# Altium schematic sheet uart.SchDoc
size A4
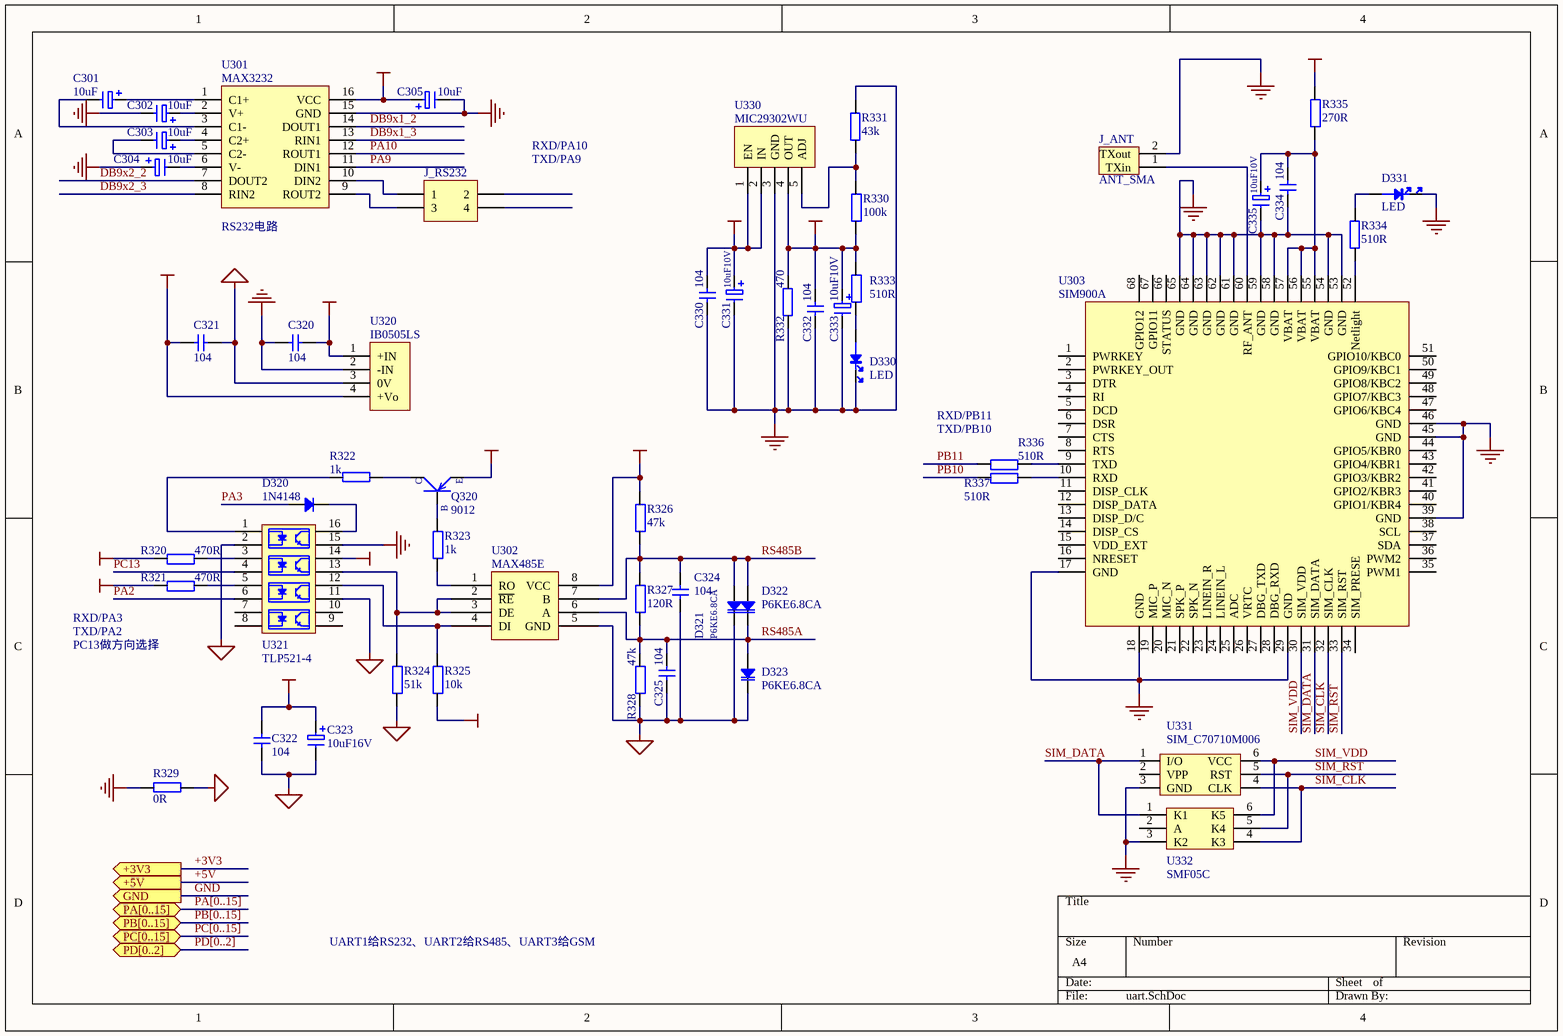
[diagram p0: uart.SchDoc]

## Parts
C301  10uF
C302  10uF
C303  10uF
C304  10uF
C305  10uF
C320  104
C321  104
C322  104
C323  10uF16V
C324  104
C325  104
C330  104
C331  10uF10V
C332  104
C333  10uF10V
C334  104
C335  10uF10V
D320  1N4148  [SOD-123]
D321  P6KE6.8CA  [SOD-123]
D322  P6KE6.8CA  [SOD-123]
D323  P6KE6.8CA  [SOD-123]
D330  LED  [SMDLED]
D331  LED  [SMDLED]
J_ANT  ANT_SMA
J_RS232  Header 2X2  [HDR2X2]  (value not drawn)
Q320  9012  [ZD_TO-92]
R320  470R  [0603P]
R321  470R  [0603P]
R322  1k  [0603P]
R323  1k  [0603P]
R324  51k  [0603P]
R325  10k  [0603P]
R326  47k  [0603P]
R327  120R  [0603P]
R328  47k  [0603P]
R329  0R  [0603P]
R330  100k  [0603P]
R331  43k  [0603P]
R332  470  [0603P]
R333  510R  [0603P]
R334  510R  [0603P]
R335  270R  [0603P]
R336  510R  [0603P]
R337  510R  [0603P]
U301  MAX3232
U302  MAX485E  [DIP8]
U303  SIM900A  [Model Name]
U320  IB0505LS  [IB0505LS]
U321  TLP521-4
U330  MIC29302WU  [TO-263]
U331  SIM_C70710M006  [SIM]
U332  SMF05C  [SOT-363]

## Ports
+3V3 (out), +5V (out), GND (out), PA[0..15] (bidir), PB[0..15] (bidir), PC[0..15] (bidir), PD[0..2] (bidir)

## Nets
+3V3: C305.1 R320.1 R321.1 U301.16(VCC) ; port +3V3
+5V: C320.2 C330.1 C331.1 U320.1(+IN) U330.1(EN) U330.2(IN) ; port +5V
GND: C302.2 C304.1 C305.2 C320.1 C330.2 C331.2 C332.2 C333.2 C334.2 C335.2 D330.2(K) D331.2(K) J_ANT.2(TXout) R329.2 R331.1 R332.2 U301.15(GND) U303.17(GND) U303.18(GND) U303.29(GND) U303.39(GND) U303.45(GND) U303.46(GND) U303.53(GND) U303.54(GND) U303.58(GND) U303.59(GND) U303.61(GND) U303.62(GND) U303.63(GND) U303.64(GND) U303.65(GND) U320.2(-IN) U321.15 U330.3(GND) U331.3(GND) U332.3(K2) ; port GND
GND485: C321.2 C322.1 C323.2 C324.1 C325.1 D321.2(K-) D323.2(K-) R324.1 R328.1 R329.1 U302.5(GND) U320.3(0V) U321.2 U321.11
V485: C321.1 C322.2 C323.1 Q320.1(E) R325.1 R326.2 U302.8(VCC) U320.4(+Vo) U321.14
VGSM: C332.1 C333.1 R330.1 R332.1 R333.2 R335.2 U330.4(OUT)
DB9x1_2: U301.14(DOUT1)
DB9x1_3: U301.13(RIN1)
DB9x2_2: U301.7(DOUT2)
DB9x2_3: U301.8(RIN2)
PA2: U321.6
PA3: D320.1(A+)
PA9: U301.11(DIN1)
PA10: U301.12(ROUT1)
PB10: R337.1
PB11: R336.1
PC13: U321.4
RS485A: C325.2 D322.2(K-) D323.1(A+) R327.1 R328.2 U302.6(A)
RS485B: C324.2 D321.1(A+) D322.1(A+) R326.1 R327.2 U302.7(B)
SIM_CLK: U303.32(SIM_CLK) U331.4(CLK) U332.4(K3)
SIM_DATA: U303.31(SIM_DATA) U331.1(I/O) U332.1(K1)
SIM_RST: U303.33(SIM_RST) U331.5(RST) U332.5(K4)
SIM_VDD: U303.30(SIM_VDD) U331.6(VCC) U332.6(K5)
NetC301_1: C301.1 U301.1(C1+)
NetC301_2: C301.2 U301.3(C1-)
NetC302_1: C302.1 U301.2(V+)
NetC303_1: C303.1 U301.4(C2+)
NetC303_2: C303.2 U301.5(C2-)
NetC304_2: C304.2 U301.6(V-)
NetC334_1: C334.1 C335.1 R335.1 U303.55(VBAT) U303.56(VBAT) U303.57(VBAT)
NetD320_2: D320.2(K-) U321.16
NetD330_1: D330.1(A) R333.1
NetD331_1: D331.1(A) R334.1
NetJ_ANT_1: J_ANT.1(TXin) U303.60(RF_ANT)
NetJ_RS232_1: J_RS232.1 U301.10(DIN2)
NetJ_RS232_3: J_RS232.3 U301.9(ROUT2)
NetQ320_2: Q320.2(B) R323.2
NetQ320_3: Q320.3(C) R322.1
NetR320_2: R320.2 U321.3
NetR321_2: R321.2 U321.5
NetR322_2: R322.2 U321.1
NetR323_1: R323.1 U302.1(RO)
NetR324_2: R324.2 U302.2(~{RE}) U302.3(DE) U321.13
NetR325_2: R325.2 U302.4(DI) U321.12
NetR330_2: R330.2 R331.2 U330.5(ADJ)
NetR334_2: R334.2 U303.52(Netlight)
NetR336_2: R336.2 U303.9(TXD)
NetR337_2: R337.2 U303.10(RXD)

Not connected (* = marked no-connect by the designer): J_RS232 2 4; U303 1(PWRKEY) 2(PWRKEY_OUT) 3(DTR) 4(RI) 5(DCD) 6(DSR) 7(CTS) 8(RTS) 11(DISP_CLK) 12(DISP_DATA) 13(DISP_D/C) 14(DISP_CS) 15(VDD_EXT) 16(NRESET) 19(MIC_P) 20(MIC_N) 21(SPK_P) 22(SPK_N) 23(LINEIN_R) 24(LINEIN_L) 25(ADC) 26(VRTC) 27(DBG_TXD) 28(DBG_RXD) 34(SIM_PRESE) 35(PWM1) 36(PWM2) 37(SDA) 38(SCL) 40(GPIO1/KBR4) 41(GPIO2/KBR3) 42(GPIO3/KBR2) 43(GPIO4/KBR1) 44(GPIO5/KBR0) 47(GPIO6/KBC4) 48(GPIO7/KBC3) 49(GPIO8/KBC2) 50(GPIO9/KBC1) 51(GPIO10/KBC0) 66(STATUS) 67(GPIO11) 68(GPIO12); U321 7 8 9 10; U331 2(VPP); U332 2(A)

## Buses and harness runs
bus PA[0..15] = port PA[0..15]
bus PB[0..15] = port PB[0..15]
bus PC[0..15] = port PC[0..15]
bus PD[0..2] = port PD[0..2]

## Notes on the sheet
- TXD/PA9
- RXD/PA10
- (near U301) RS232电路
- TXD/PB10
- RXD/PB11
- PC13做方向选择
- RXD/PA3
- TXD/PA2
- UART1给RS232、UART2给RS485、UART3给GSM

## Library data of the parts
C301-C305 = ELECTRO_MIN
C320-C322 C324 C325 C330 C332 C334 = CAP: Capacitor
C323 C331 C333 C335 = ELECTRO_MIN_2
D320 = DIODE
D321-D323 = DIODE_TVS
D330 D331 = LED_MIN
J_ANT = ANT1
J_RS232 = Header 2X2: Header, 2-Pin, Dual row
Q320 = PNP_MIN_1
R320-R337 = RES
U331 = SIM_C70710M006: SIM_Card
U332 = SMF05C: TVS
